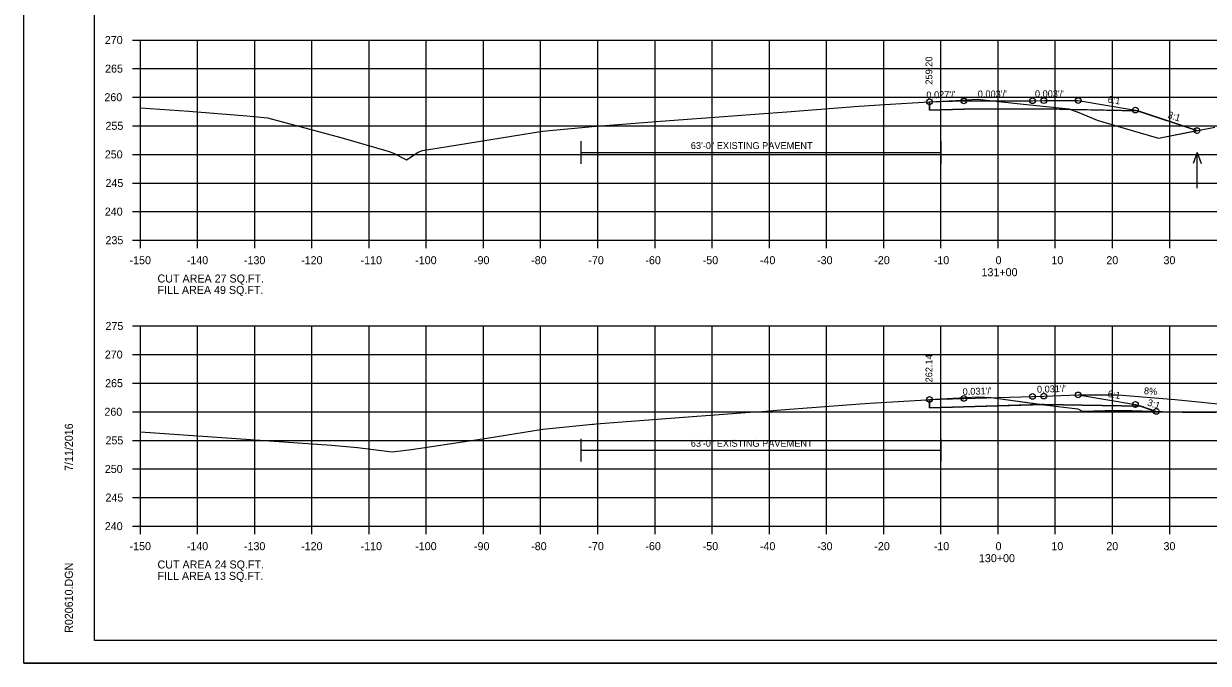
# Model space of a CAD drawing. Extents: x 1103485 to 1107180, y 2010593 to 2011873.
# Drawn here: x 1106846.8 to 1107053.9, y 2011232.8 to 2011344.7 of the extents above; entities that cross this region are included whole.
import ezdxf

# ---------------------------------------------------------------- set-up
doc = ezdxf.new("R2010")
doc.units = 0
for name, color, linetype in [('R_Alt Surface', 7, 'Continuous'), ('R_Axis', 7, 'Continuous'), ('R_Axis Annot', 7, 'Continuous'), ('R_Border', 7, 'Continuous'), ('R_Contours', 7, 'Continuous'), ('R_Dimension', 7, 'Continuous'), ('R_Drive', 7, 'Continuous'), ('R_Exist Surface', 7, 'Continuous'), ('R_Fin Surface', 7, 'Continuous'), ('R_Grid', 7, 'Continuous'), ('R_No Plot', 7, 'Continuous'), ('R_Proposed Const Limits', 7, 'Continuous'), ('R_Water Annot', 7, 'Continuous'), ('R_Xsect Elev', 7, 'Continuous'), ('R_Xsect Slope', 7, 'Continuous')]:
    doc.layers.add(name, color=color, linetype=linetype)

msp = doc.modelspace()

# ---------------------------------------------------------------- linework, layer by layer
at = {"layer": 'R_Alt Surface'}
for points in [[(1107005.18, 2011331.03), (1107005.18, 2011329.57), (1107011.18, 2011329.73), (1107025.18, 2011329.77), (1107041.6, 2011329.44)], [(1107005.18, 2011278.97), (1107005.18, 2011277.51), (1107011.18, 2011277.7), (1107025.18, 2011278.12), (1107042.13, 2011277.79)]]:
    msp.add_lwpolyline(points, dxfattribs=at)
at = {"layer": 'R_Axis'}
for p, q in [((1106865.78, 2011341.83), (1106867.18, 2011341.83)), ((1106867.18, 2011306.83), (1106867.18, 2011341.83)), ((1106865.78, 2011336.83), (1106867.18, 2011336.83)), ((1106865.78, 2011331.83), (1106867.18, 2011331.83)), ((1106865.78, 2011326.83), (1106867.18, 2011326.83)), ((1106865.78, 2011321.83), (1106867.18, 2011321.83)), ((1106865.78, 2011316.83), (1106867.18, 2011316.83)), ((1106865.78, 2011311.83), (1106867.18, 2011311.83)), ((1106865.78, 2011306.83), (1106867.18, 2011306.83)), ((1106867.18, 2011306.83), (1107167.18, 2011306.83)), ((1106867.18, 2011305.43), (1106867.18, 2011306.83)), ((1106877.18, 2011305.43), (1106877.18, 2011306.83)), ((1106887.18, 2011305.43), (1106887.18, 2011306.83)), ((1106897.18, 2011305.43), (1106897.18, 2011306.83)), ((1106907.18, 2011305.43), (1106907.18, 2011306.83)), ((1106917.18, 2011305.43), (1106917.18, 2011306.83)), ((1106927.18, 2011305.43), (1106927.18, 2011306.83)), ((1106937.18, 2011305.43), (1106937.18, 2011306.83)), ((1106947.18, 2011305.43), (1106947.18, 2011306.83)), ((1106957.18, 2011305.43), (1106957.18, 2011306.83)), ((1106967.18, 2011305.43), (1106967.18, 2011306.83)), ((1106977.18, 2011305.43), (1106977.18, 2011306.83)), ((1106987.18, 2011305.43), (1106987.18, 2011306.83)), ((1106997.18, 2011305.43), (1106997.18, 2011306.83)), ((1107007.18, 2011305.43), (1107007.18, 2011306.83)), ((1107017.18, 2011305.43), (1107017.18, 2011306.83)), ((1107027.18, 2011305.43), (1107027.18, 2011306.83)), ((1107037.18, 2011305.43), (1107037.18, 2011306.83)), ((1107047.18, 2011305.43), (1107047.18, 2011306.83)), ((1106865.78, 2011291.83), (1106867.18, 2011291.83)), ((1106867.18, 2011256.83), (1106867.18, 2011291.83)), ((1106865.78, 2011286.83), (1106867.18, 2011286.83)), ((1106865.78, 2011281.83), (1106867.18, 2011281.83)), ((1106865.78, 2011276.83), (1106867.18, 2011276.83)), ((1106865.78, 2011271.83), (1106867.18, 2011271.83)), ((1106865.78, 2011266.83), (1106867.18, 2011266.83)), ((1106865.78, 2011261.83), (1106867.18, 2011261.83)), ((1106865.78, 2011256.83), (1106867.18, 2011256.83)), ((1106867.18, 2011256.83), (1107167.18, 2011256.83)), ((1106867.18, 2011255.43), (1106867.18, 2011256.83)), ((1106877.18, 2011255.43), (1106877.18, 2011256.83)), ((1106887.18, 2011255.43), (1106887.18, 2011256.83)), ((1106897.18, 2011255.43), (1106897.18, 2011256.83)), ((1106907.18, 2011255.43), (1106907.18, 2011256.83)), ((1106917.18, 2011255.43), (1106917.18, 2011256.83)), ((1106927.18, 2011255.43), (1106927.18, 2011256.83)), ((1106937.18, 2011255.43), (1106937.18, 2011256.83)), ((1106947.18, 2011255.43), (1106947.18, 2011256.83)), ((1106957.18, 2011255.43), (1106957.18, 2011256.83)), ((1106967.18, 2011255.43), (1106967.18, 2011256.83)), ((1106977.18, 2011255.43), (1106977.18, 2011256.83)), ((1106987.18, 2011255.43), (1106987.18, 2011256.83)), ((1106997.18, 2011255.43), (1106997.18, 2011256.83)), ((1107007.18, 2011255.43), (1107007.18, 2011256.83)), ((1107017.18, 2011255.43), (1107017.18, 2011256.83)), ((1107027.18, 2011255.43), (1107027.18, 2011256.83)), ((1107037.18, 2011255.43), (1107037.18, 2011256.83)), ((1107047.18, 2011255.43), (1107047.18, 2011256.83))]:
    msp.add_line(p, q, dxfattribs=at)
at = {"layer": 'R_Border'}
for p, q in [((1106859.18, 2011236.83), (1106859.18, 2011442.29)), ((1106859.18, 2011236.83), (1106859.18, 2011236.83)), ((1107175.36, 2011236.83), (1106859.18, 2011236.83))]:
    msp.add_line(p, q, dxfattribs=at)
at = {"layer": 'R_Contours'}
for points in [[(1107005.18, 2011331.03), (1107009.79, 2011331.28), (1107013.57, 2011331.5), (1107020.48, 2011330.73), (1107029.55, 2011329.78), (1107029.84, 2011329.68), (1107025.18, 2011329.77), (1107011.18, 2011329.73), (1107005.18, 2011329.57)], [(1107029.84, 2011329.68), (1107031.28, 2011329.16), (1107034.48, 2011327.79), (1107040.22, 2011326.12), (1107045.24, 2011324.65), (1107051.95, 2011325.99), (1107041.6, 2011329.44)], [(1107005.18, 2011278.96), (1107009.32, 2011279.21), (1107013.62, 2011279.46), (1107013.62, 2011279.46), (1107015.95, 2011279.33), (1107024.79, 2011278.11), (1107011.18, 2011277.7), (1107005.18, 2011277.51)], [(1107024.79, 2011278.11), (1107026.22, 2011277.91), (1107031.09, 2011277.33), (1107031.85, 2011276.94), (1107035.9, 2011277.04), (1107040.57, 2011277.03), (1107044.83, 2011276.89), (1107042.13, 2011277.79), (1107025.18, 2011278.12)]]:
    msp.add_lwpolyline(points, close=True, dxfattribs=at)
at = {"layer": 'R_Dimension'}
for p, q in [((1106944.18, 2011324.17), (1106944.18, 2011320.17)), ((1107007.18, 2011324.17), (1107007.18, 2011320.17)), ((1106944.18, 2011322.17), (1107007.18, 2011322.17)), ((1106944.18, 2011272.11), (1106944.18, 2011268.11)), ((1107007.18, 2011272.11), (1107007.18, 2011268.11)), ((1106944.18, 2011270.11), (1107007.18, 2011270.11))]:
    msp.add_line(p, q, dxfattribs=at)
at = {"layer": 'R_Drive'}
for p, q in [((1107031.18, 2011279.77), (1107038.18, 2011279.77)), ((1107038.18, 2011279.77), (1107048.15, 2011278.97)), ((1107048.15, 2011278.97), (1107076.2, 2011276.17))]:
    msp.add_line(p, q, dxfattribs=at)
at = {"layer": 'R_Exist Surface'}
for points in [[(1106867.18, 2011329.99), (1106875.68, 2011329.41), (1106885.77, 2011328.6), (1106889.39, 2011328.21), (1106902.21, 2011324.77), (1106910.7, 2011322.36), (1106911.45, 2011322.06), (1106913.71, 2011320.88), (1106915.74, 2011322.21), (1106916.5, 2011322.54), (1106920.87, 2011323.22), (1106937.53, 2011325.89), (1106944.39, 2011326.53), (1106946.17, 2011326.7), (1106947.75, 2011326.82), (1106958.12, 2011327.63), (1106970.76, 2011328.56), (1106975.38, 2011328.9), (1106980.23, 2011329.28), (1106992.82, 2011330.28), (1106997.37, 2011330.55), (1107005.1, 2011331.02), (1107009.79, 2011331.28), (1107013.57, 2011331.5), (1107020.48, 2011330.73), (1107029.55, 2011329.78), (1107031.28, 2011329.16), (1107034.48, 2011327.79), (1107040.22, 2011326.12), (1107045.24, 2011324.65), (1107055.06, 2011326.62)], [(1106867.18, 2011273.34), (1106886.42, 2011272), (1106900.6, 2011270.99), (1106905.16, 2011270.56), (1106911.2, 2011269.8), (1106914.58, 2011270.25), (1106918.49, 2011270.79), (1106927.79, 2011272.24), (1106937.56, 2011273.8), (1106946.22, 2011274.65), (1106946.5, 2011274.67), (1106946.89, 2011274.7), (1106958.31, 2011275.58), (1106974.57, 2011276.79), (1106975.23, 2011276.84), (1106979.2, 2011277.15), (1106993.05, 2011278.23), (1106994.75, 2011278.34), (1107004.64, 2011278.93), (1107009.32, 2011279.21), (1107013.62, 2011279.46), (1107013.62, 2011279.46), (1107015.95, 2011279.33), (1107026.22, 2011277.91), (1107031.09, 2011277.33), (1107031.85, 2011276.94), (1107035.9, 2011277.04), (1107040.57, 2011277.03), (1107049.38, 2011276.74), (1107052.46, 2011276.76), (1107055.19, 2011276.7)]]:
    msp.add_lwpolyline(points, dxfattribs=at)
at = {"layer": 'R_Fin Surface'}
for points in [[(1107005.18, 2011331.03), (1107011.18, 2011331.19), (1107023.18, 2011331.22), (1107025.18, 2011331.23), (1107031.18, 2011331.25), (1107041.18, 2011329.58), (1107041.6, 2011329.44), (1107051.95, 2011325.99)], [(1107005.18, 2011331.03), (1107011.18, 2011331.19), (1107023.18, 2011331.22), (1107025.18, 2011331.23), (1107031.18, 2011331.25)], [(1107005.18, 2011278.97), (1107011.18, 2011279.16), (1107023.18, 2011279.52), (1107025.18, 2011279.58), (1107031.18, 2011279.77), (1107041.18, 2011278.1), (1107042.13, 2011277.79), (1107044.83, 2011276.89)], [(1107005.18, 2011278.97), (1107011.18, 2011279.16), (1107023.18, 2011279.52), (1107025.18, 2011279.58), (1107031.18, 2011279.77)]]:
    msp.add_lwpolyline(points, dxfattribs=at)
at = {"layer": 'R_Grid'}
for p, q in [((1106867.18, 2011341.83), (1107167.18, 2011341.83)), ((1106867.18, 2011306.83), (1106867.18, 2011341.83)), ((1106877.18, 2011306.83), (1106877.18, 2011341.83)), ((1106887.18, 2011306.83), (1106887.18, 2011341.83)), ((1106897.18, 2011306.83), (1106897.18, 2011341.83)), ((1106907.18, 2011306.83), (1106907.18, 2011341.83)), ((1106917.18, 2011306.83), (1106917.18, 2011341.83)), ((1106927.18, 2011306.83), (1106927.18, 2011341.83)), ((1106937.18, 2011306.83), (1106937.18, 2011341.83)), ((1106947.18, 2011306.83), (1106947.18, 2011341.83)), ((1106957.18, 2011306.83), (1106957.18, 2011341.83)), ((1106967.18, 2011306.83), (1106967.18, 2011341.83)), ((1106977.18, 2011306.83), (1106977.18, 2011341.83)), ((1106987.18, 2011306.83), (1106987.18, 2011341.83)), ((1106997.18, 2011306.83), (1106997.18, 2011341.83)), ((1107007.18, 2011306.83), (1107007.18, 2011341.83)), ((1107017.18, 2011306.83), (1107017.18, 2011341.83)), ((1107027.18, 2011306.83), (1107027.18, 2011341.83)), ((1107037.18, 2011306.83), (1107037.18, 2011341.83)), ((1107047.18, 2011306.83), (1107047.18, 2011341.83)), ((1106867.18, 2011336.83), (1107167.18, 2011336.83)), ((1106867.18, 2011331.83), (1107167.18, 2011331.83)), ((1106867.18, 2011326.83), (1107167.18, 2011326.83)), ((1106867.18, 2011321.83), (1107167.18, 2011321.83)), ((1106867.18, 2011316.83), (1107167.18, 2011316.83)), ((1106867.18, 2011311.83), (1107167.18, 2011311.83)), ((1106867.18, 2011306.83), (1107167.18, 2011306.83)), ((1106867.18, 2011291.83), (1107167.18, 2011291.83)), ((1106867.18, 2011256.83), (1106867.18, 2011291.83)), ((1106877.18, 2011256.83), (1106877.18, 2011291.83)), ((1106887.18, 2011256.83), (1106887.18, 2011291.83)), ((1106897.18, 2011256.83), (1106897.18, 2011291.83)), ((1106907.18, 2011256.83), (1106907.18, 2011291.83)), ((1106917.18, 2011256.83), (1106917.18, 2011291.83)), ((1106927.18, 2011256.83), (1106927.18, 2011291.83)), ((1106937.18, 2011256.83), (1106937.18, 2011291.83)), ((1106947.18, 2011256.83), (1106947.18, 2011291.83)), ((1106957.18, 2011256.83), (1106957.18, 2011291.83)), ((1106967.18, 2011256.83), (1106967.18, 2011291.83)), ((1106977.18, 2011256.83), (1106977.18, 2011291.83)), ((1106987.18, 2011256.83), (1106987.18, 2011291.83)), ((1106997.18, 2011256.83), (1106997.18, 2011291.83)), ((1107007.18, 2011256.83), (1107007.18, 2011291.83)), ((1107017.18, 2011256.83), (1107017.18, 2011291.83)), ((1107027.18, 2011256.83), (1107027.18, 2011291.83)), ((1107037.18, 2011256.83), (1107037.18, 2011291.83)), ((1107047.18, 2011256.83), (1107047.18, 2011291.83)), ((1106867.18, 2011286.83), (1107167.18, 2011286.83)), ((1106867.18, 2011281.83), (1107167.18, 2011281.83)), ((1106867.18, 2011276.83), (1107167.18, 2011276.83)), ((1106867.18, 2011271.83), (1107167.18, 2011271.83)), ((1106867.18, 2011266.83), (1107167.18, 2011266.83)), ((1106867.18, 2011261.83), (1107167.18, 2011261.83)), ((1106867.18, 2011256.83), (1107167.18, 2011256.83))]:
    msp.add_line(p, q, dxfattribs=at)
at = {"layer": 'R_No Plot'}
msp.add_line((1106846.78, 2011232.85), (1107180.12, 2011232.85), dxfattribs=at)
for points in [[(1106846.78, 2011446.19), (1107180.12, 2011446.19), (1107180.12, 2011232.85), (1106846.78, 2011232.85)], [(1107093.1, 2011442.29), (1107093.1, 2011432.41), (1107128.84, 2011432.41), (1107128.84, 2011429.49), (1107152.04, 2011429.49), (1107152.04, 2011405.16), (1107175.36, 2011405.16), (1107175.36, 2011236.83), (1106859.18, 2011236.83), (1106859.18, 2011442.29)]]:
    msp.add_lwpolyline(points, close=True, dxfattribs=at)
for centre in [(1107005.18, 2011331.03), (1107011.18, 2011331.19), (1107023.18, 2011331.22), (1107025.18, 2011331.23), (1107031.18, 2011331.25), (1107041.18, 2011329.58), (1107051.95, 2011325.99), (1107031.18, 2011279.77), (1107005.18, 2011278.97), (1107011.18, 2011279.16), (1107023.18, 2011279.52), (1107025.18, 2011279.58), (1107041.18, 2011278.1), (1107044.83, 2011276.89)]:
    msp.add_circle(centre, 0.5, dxfattribs=at)
at = {"layer": 'R_Proposed Const Limits'}
for points in [[(1107031.18, 2011331.25), (1107041.18, 2011329.58), (1107051.95, 2011325.99)], [(1107031.18, 2011279.77), (1107041.18, 2011278.1), (1107044.83, 2011276.89)]]:
    msp.add_lwpolyline(points, dxfattribs=at)
at = {"layer": 'R_Water Annot'}
for p, q in [((1107051.98, 2011322.18), (1107051.28, 2011320.26)), ((1107051.98, 2011315.9), (1107051.98, 2011322.18)), ((1107051.98, 2011322.18), (1107052.68, 2011320.26))]:
    msp.add_line(p, q, dxfattribs=at)

# ---------------------------------------------------------------- texts
at = {"layer": 'R_Axis Annot'}
for s, p in [('270', (1106860.96, 2011341.13)), ('265', (1106861.01, 2011336.13)), ('260', (1106860.89, 2011331.13)), ('255', (1106861.08, 2011326.13)), ('250', (1106860.96, 2011321.13)), ('245', (1106861.08, 2011316.13)), ('240', (1106860.96, 2011311.13)), ('235', (1106861.08, 2011306.13)), ('-150', (1106865.29, 2011302.63)), ('-140', (1106875.29, 2011302.63)), ('-130', (1106885.29, 2011302.63)), ('-120', (1106895.29, 2011302.63)), ('-110', (1106905.69, 2011302.63)), ('-100', (1106915.24, 2011302.63)), ('-90', (1106925.52, 2011302.63)), ('-80', (1106935.52, 2011302.63)), ('-70', (1106945.52, 2011302.63)), ('-60', (1106955.49, 2011302.63)), ('-50', (1106965.52, 2011302.63)), ('-40', (1106975.52, 2011302.63)), ('-30', (1106985.52, 2011302.63)), ('-20', (1106995.52, 2011302.63)), ('-10', (1107005.92, 2011302.63)), ('0', (1107016.73, 2011302.63)), ('10', (1107026.49, 2011302.63)), ('20', (1107036.1, 2011302.63)), ('30', (1107046.1, 2011302.63)), ('131+00', (1107014.27, 2011300.53)), ('CUT AREA 27 SQ.FT.', (1106870.18, 2011299.43)), ('FILL AREA 49 SQ.FT.', (1106870.18, 2011297.43)), ('275', (1106861.08, 2011291.13)), ('270', (1106860.96, 2011286.13)), ('265', (1106861.01, 2011281.13)), ('260', (1106860.89, 2011276.13)), ('255', (1106861.08, 2011271.13)), ('250', (1106860.96, 2011266.13)), ('245', (1106861.08, 2011261.13)), ('240', (1106860.96, 2011256.13)), ('-150', (1106865.29, 2011252.63)), ('-140', (1106875.29, 2011252.63)), ('-130', (1106885.29, 2011252.63)), ('-120', (1106895.29, 2011252.63)), ('-110', (1106905.69, 2011252.63)), ('-100', (1106915.24, 2011252.63)), ('-90', (1106925.52, 2011252.63)), ('-80', (1106935.52, 2011252.63)), ('-70', (1106945.52, 2011252.63)), ('-60', (1106955.49, 2011252.63)), ('-50', (1106965.52, 2011252.63)), ('-40', (1106975.52, 2011252.63)), ('-30', (1106985.52, 2011252.63)), ('-20', (1106995.52, 2011252.63)), ('-10', (1107005.92, 2011252.63)), ('0', (1107016.73, 2011252.63)), ('10', (1107026.49, 2011252.63)), ('20', (1107036.1, 2011252.63)), ('30', (1107046.1, 2011252.63)), ('130+00', (1107013.82, 2011250.53)), ('CUT AREA 24 SQ.FT.', (1106870.18, 2011249.43)), ('FILL AREA 13 SQ.FT.', (1106870.18, 2011247.43))]:
    msp.add_text(s, height=1.4, dxfattribs=at).set_placement(p)
at = {"layer": 'R_Border'}
for s, p in [('7/11/2016', (1106855.37, 2011266.47)), ('R020610.DGN', (1106855.37, 2011238.16))]:
    msp.add_text(s, height=1.4, rotation=90, dxfattribs=at).set_placement(p)
at = {"layer": 'R_Dimension'}
for p in [(1106963.44, 2011322.77), (1106963.44, 2011270.71)]:
    msp.add_text('63\'-0" EXISTING PAVEMENT', height=1.2, dxfattribs=at).set_placement(p)
at = {"layer": 'R_Drive'}
msp.add_text('8%', height=1.2, rotation=355.426, dxfattribs=at).set_placement((1107042.64, 2011279.92))
at = {"layer": 'R_Xsect Elev'}
for s, p in [('259.20', (1107005.68, 2011334.03)), ('262.14', (1107005.68, 2011281.97))]:
    msp.add_text(s, height=1.2, rotation=90, dxfattribs=at).set_placement(p)
at = {"layer": 'R_Xsect Slope'}
for s, rotation, p in [("0.027'/'", 1.5466, (1107004.65, 2011331.61)), ("0.003'/'", 0.1634, (1107013.62, 2011331.8)), ("0.003'/'", 0.1634, (1107023.62, 2011331.83)), ('6:1', 350.5358, (1107036.27, 2011330.91)), ('3:1', 341.5668, (1107046.72, 2011328.26)), ("0.031'/'", 1.7552, (1107010.99, 2011279.75)), ("0.031'/'", 1.756, (1107023.99, 2011280.15)), ('6:1', 350.5358, (1107036.27, 2011279.43)), ('3:1', 341.5668, (1107043.16, 2011277.97))]:
    msp.add_text(s, height=1.2, rotation=rotation, dxfattribs=at).set_placement(p)

doc.saveas('drawing.dxf')
